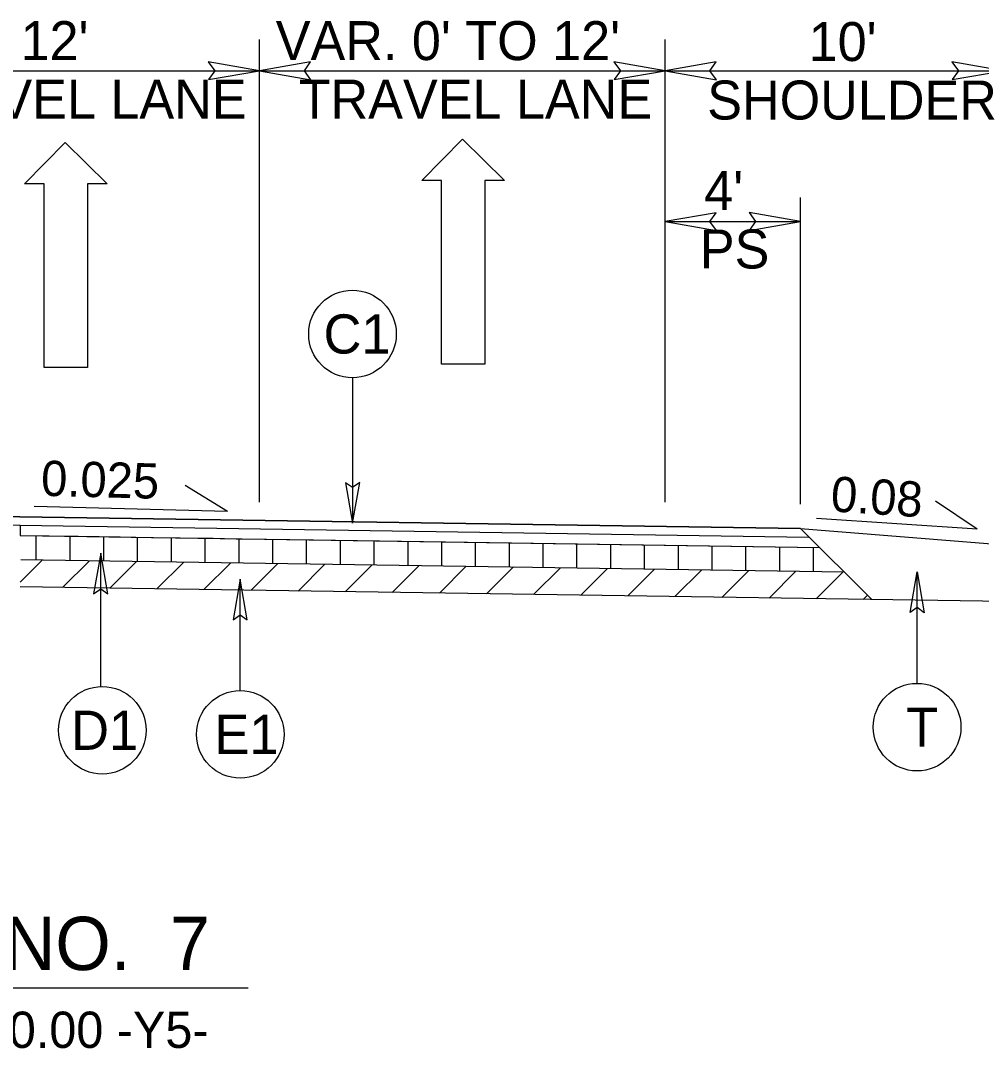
# Model space of a CAD drawing. Extents: x 2176156 to 2177167, y 76401 to 76644.
# Drawn here: x 2176302.62 to 2176331.05, y 76503.74 to 76534.15 of the extents above; entities that cross this region are included whole.
import ezdxf

# ---------------------------------------------------------------- set-up
doc = ezdxf.new("R2010")
doc.units = 0
for name, color, linetype in [('Exist Building', 7, 'Continuous'), ('Exist Building Metal Canopy', 7, 'Continuous'), ('Exist Roads Curbs', 7, 'Continuous'), ('Exist Roads EOP Other', 7, 'Continuous'), ('Exist Roads Soil', 7, 'Continuous'), ('Exist Structure Minor Culvert Topo', 7, 'Continuous'), ('Exist Structure Minor Drop Inlet', 7, 'Continuous'), ('Exist Utilities Other Pole CELL', 7, 'Continuous'), ('Exist Vegetation Woods Line', 7, 'Continuous'), ('Model Boundary Lines Text', 7, 'Continuous'), ('Old_Level_1', 7, 'Continuous'), ('Old_Level_3', 7, 'Continuous'), ('Prop North Arrow NAD83 for Plan Sheets CELL', 7, 'Continuous')]:
    doc.layers.add(name, color=color, linetype=linetype)

msp = doc.modelspace()

# ---------------------------------------------------------------- linework, layer by layer
at = {"layer": 'Exist Building'}
msp.add_line((2176342.792, 76516.795), (2176302.609, 76517.393), dxfattribs=at)
at = {"layer": 'Exist Roads Curbs'}
for p, q in [((2176295.689, 76519.569), (2176325.689, 76519.123)), ((2176296.361, 76519.309), (2176325.944, 76518.869))]:
    msp.add_line(p, q, dxfattribs=at)
at = {"layer": 'Exist Roads EOP Other'}
for p, q in [((2176325.689, 76519.123), (2176296.41, 76519.558)), ((2176325.689, 76519.123), (2176331.724, 76518.64)), ((2176326.252, 76518.563), (2176325.689, 76519.123)), ((2176311.28, 76518.785), (2176326.252, 76518.563))]:
    msp.add_line(p, q, dxfattribs=at)
msp.add_lwpolyline([(2176296.361, 76519.309), (2176302.609, 76519.216), (2176302.609, 76518.915), (2176304.319, 76518.89), (2176305.566, 76518.871), (2176306.49, 76518.858), (2176307.341, 76518.845), (2176308.316, 76518.83), (2176308.997, 76518.82), (2176309.894, 76518.807), (2176311.28, 76518.785)], dxfattribs=at)
at = {"layer": 'Exist Roads Soil'}
for p, q in [((2176325.689, 76519.123), (2176327.805, 76517.018)), ((2176302.609, 76518.915), (2176326.252, 76518.563)), ((2176302.621, 76518.199), (2176326.982, 76517.837))]:
    msp.add_line(p, q, dxfattribs=at)
at = {"layer": 'Exist Structure Minor Drop Inlet'}
for p, q in [((2176314.486, 76529.419), (2176315.689, 76530.641)), ((2176315.689, 76530.641), (2176316.931, 76529.419)), ((2176302.733, 76529.314), (2176303.936, 76530.536)), ((2176303.936, 76530.536), (2176305.177, 76529.314)), ((2176315.068, 76529.419), (2176314.486, 76529.419)), ((2176315.068, 76523.987), (2176315.068, 76529.419)), ((2176316.931, 76529.419), (2176316.349, 76529.419)), ((2176316.349, 76529.419), (2176316.349, 76523.987)), ((2176303.315, 76529.314), (2176302.733, 76529.314)), ((2176303.315, 76523.882), (2176303.315, 76529.314)), ((2176305.177, 76529.314), (2176304.595, 76529.314)), ((2176304.595, 76529.314), (2176304.595, 76523.882)), ((2176316.349, 76523.987), (2176315.068, 76523.987)), ((2176304.595, 76523.882), (2176303.315, 76523.882))]:
    msp.add_line(p, q, dxfattribs=at)
at = {"layer": 'Exist Utilities Other Pole CELL'}
for p, q in [((2176308.739, 76519.624), (2176307.482, 76520.394)), ((2176308.739, 76519.624), (2176303.014, 76519.773)), ((2176330.917, 76519.106), (2176329.692, 76519.925)), ((2176330.917, 76519.106), (2176326.171, 76519.419))]:
    msp.add_line(p, q, dxfattribs=at)
at = {"layer": 'Model Boundary Lines Text'}
for p, q in [((2176303.08, 76518.193), (2176303.08, 76518.908)), ((2176304.08, 76518.178), (2176304.08, 76518.894)), ((2176305.08, 76518.163), (2176305.08, 76518.879)), ((2176306.08, 76518.148), (2176306.08, 76518.864)), ((2176307.08, 76518.133), (2176307.08, 76518.849)), ((2176308.08, 76518.118), (2176308.08, 76518.834)), ((2176309.08, 76518.103), (2176309.08, 76518.819)), ((2176310.08, 76518.088), (2176310.08, 76518.804)), ((2176311.08, 76518.074), (2176311.08, 76518.789)), ((2176312.08, 76518.059), (2176312.08, 76518.774)), ((2176313.08, 76518.044), (2176313.08, 76518.76)), ((2176314.08, 76518.029), (2176314.08, 76518.745)), ((2176315.08, 76518.014), (2176315.08, 76518.73)), ((2176316.08, 76517.999), (2176316.08, 76518.715)), ((2176317.08, 76517.984), (2176317.08, 76518.7)), ((2176318.08, 76517.969), (2176318.08, 76518.685)), ((2176319.08, 76517.954), (2176319.08, 76518.67)), ((2176320.08, 76517.94), (2176320.08, 76518.655)), ((2176321.08, 76517.925), (2176321.08, 76518.64)), ((2176322.08, 76517.91), (2176322.08, 76518.626)), ((2176323.08, 76517.895), (2176323.08, 76518.611)), ((2176324.08, 76517.88), (2176324.08, 76518.596)), ((2176325.08, 76517.865), (2176325.08, 76518.581)), ((2176326.08, 76517.85), (2176326.08, 76518.566)), ((2176302.609, 76517.536), (2176303.262, 76518.19)), ((2176303.861, 76517.375), (2176304.656, 76518.169)), ((2176305.255, 76517.354), (2176306.049, 76518.148)), ((2176306.648, 76517.333), (2176307.443, 76518.128)), ((2176308.042, 76517.312), (2176308.836, 76518.107)), ((2176309.435, 76517.292), (2176310.23, 76518.086)), ((2176310.829, 76517.271), (2176311.623, 76518.065)), ((2176312.222, 76517.25), (2176313.017, 76518.045)), ((2176313.616, 76517.23), (2176314.41, 76518.024)), ((2176315.009, 76517.209), (2176315.804, 76518.003)), ((2176316.403, 76517.188), (2176317.197, 76517.983)), ((2176317.796, 76517.167), (2176318.59, 76517.962)), ((2176319.189, 76517.147), (2176319.984, 76517.941)), ((2176320.583, 76517.126), (2176321.377, 76517.92)), ((2176321.976, 76517.105), (2176322.771, 76517.9)), ((2176323.37, 76517.084), (2176324.164, 76517.879)), ((2176324.763, 76517.064), (2176325.558, 76517.858)), ((2176326.157, 76517.043), (2176326.951, 76517.837)), ((2176327.55, 76517.022), (2176327.676, 76517.147)), ((2176282.028, 76505.529), (2176309.35, 76505.529))]:
    msp.add_line(p, q, dxfattribs=at)
at = {"layer": 'Old_Level_1'}
for points in [[(2176308.179, 76532.402), (2176309.689, 76532.662), (2176308.171, 76532.93), (2176308.364, 76532.662)], [(2176311.199, 76532.922), (2176309.689, 76532.662), (2176311.207, 76532.393), (2176311.014, 76532.662)], [(2176320.179, 76532.402), (2176321.689, 76532.662), (2176320.171, 76532.93), (2176320.364, 76532.662)], [(2176323.199, 76532.922), (2176321.689, 76532.662), (2176323.207, 76532.393), (2176323.014, 76532.662)], [(2176330.179, 76532.402), (2176331.689, 76532.662), (2176330.171, 76532.93), (2176330.364, 76532.662)], [(2176323.199, 76528.461), (2176321.689, 76528.201), (2176323.207, 76527.933), (2176323.014, 76528.201)], [(2176324.179, 76527.941), (2176325.689, 76528.201), (2176324.171, 76528.47), (2176324.364, 76528.201)]]:
    msp.add_lwpolyline(points, close=True, dxfattribs=at)
at = {"layer": 'Old_Level_3'}
for p, q in [((2176309.689, 76519.902), (2176309.689, 76533.589)), ((2176321.689, 76519.902), (2176321.689, 76533.589)), ((2176295.689, 76532.662), (2176359.676, 76532.662)), ((2176325.689, 76519.836), (2176325.689, 76528.911)), ((2176325.689, 76519.902), (2176325.689, 76528.911)), ((2176321.689, 76528.201), (2176325.689, 76528.201))]:
    msp.add_line(p, q, dxfattribs=at)
at = {"layer": 'Prop North Arrow NAD83 for Plan Sheets CELL'}
for p, q in [((2176312.437, 76523.579), (2176312.437, 76519.276)), ((2176304.989, 76514.447), (2176304.989, 76518.392)), ((2176329.143, 76514.54), (2176329.143, 76517.836)), ((2176309.118, 76514.325), (2176309.118, 76517.621))]:
    msp.add_line(p, q, dxfattribs=at)
for points in [[(2176312.23, 76520.476), (2176312.437, 76519.276), (2176312.65, 76520.483), (2176312.437, 76520.33)], [(2176305.195, 76517.192), (2176304.989, 76518.392), (2176304.775, 76517.186), (2176304.989, 76517.339)], [(2176328.936, 76516.636), (2176329.143, 76517.836), (2176329.356, 76516.629), (2176329.143, 76516.782)], [(2176309.325, 76516.421), (2176309.118, 76517.621), (2176308.905, 76516.414), (2176309.118, 76516.567)]]:
    msp.add_lwpolyline(points, close=True, dxfattribs=at)
for centre in [(2176312.437, 76524.875), (2176329.143, 76513.244), (2176305.035, 76513.152), (2176309.118, 76513.029)]:
    msp.add_circle(centre, 1.296, dxfattribs=at)

# ---------------------------------------------------------------- texts
at = {"layer": 'Exist Building Metal Canopy'}
msp.add_text('TYPICAL SECTION NO.  7', height=1.5766, rotation=0, dxfattribs=at).set_placement((2176282.793, 76506.057))
at = {"layer": 'Exist Structure Minor Culvert Topo'}
for s, height, p in [("12'", 1.1533, (2176302.616, 76532.977)), ("VAR. 0' TO 12'", 1.15334, (2176310.167, 76532.977)), ("10' ", 1.1533, (2176325.935, 76532.95)), ('TRAVEL LANE', 1.15334, (2176298.846, 76531.247)), ('TRAVEL LANE', 1.15334, (2176310.846, 76531.247)), ('SHOULDER', 1.1533, (2176322.934, 76531.22)), ("4' ", 1.1533, (2176322.845, 76528.543)), ('PS', 1.1533, (2176322.715, 76526.813))]:
    msp.add_text(s, height=height, dxfattribs=at).set_placement(p)
at = {"layer": 'Exist Utilities Other Pole CELL'}
for s, rotation, p in [('0.025', 358.5068, (2176303.214, 76520.09)), ('0.08', 356.2199, (2176326.567, 76519.63))]:
    msp.add_text(s, height=1.0429, rotation=rotation, dxfattribs=at).set_placement(p)
at = {"layer": 'Exist Vegetation Woods Line'}
msp.add_text('STA. 10+54.20 -Y5- TO STA. 23+00.00 -Y5-', height=1.0742, dxfattribs=at).set_placement((2176279.913, 76503.754))
at = {"layer": 'Prop North Arrow NAD83 for Plan Sheets CELL'}
for s, rotation, p in [('C1', 359.9997, (2176311.581, 76524.295)), ('D1', 359.9997, (2176304.114, 76512.572)), ('E1', 359.9997, (2176308.354, 76512.449)), ('T', 0.0003, (2176328.816, 76512.664))]:
    msp.add_text(s, height=1.16, rotation=rotation, dxfattribs=at).set_placement(p)

doc.saveas('drawing.dxf')
